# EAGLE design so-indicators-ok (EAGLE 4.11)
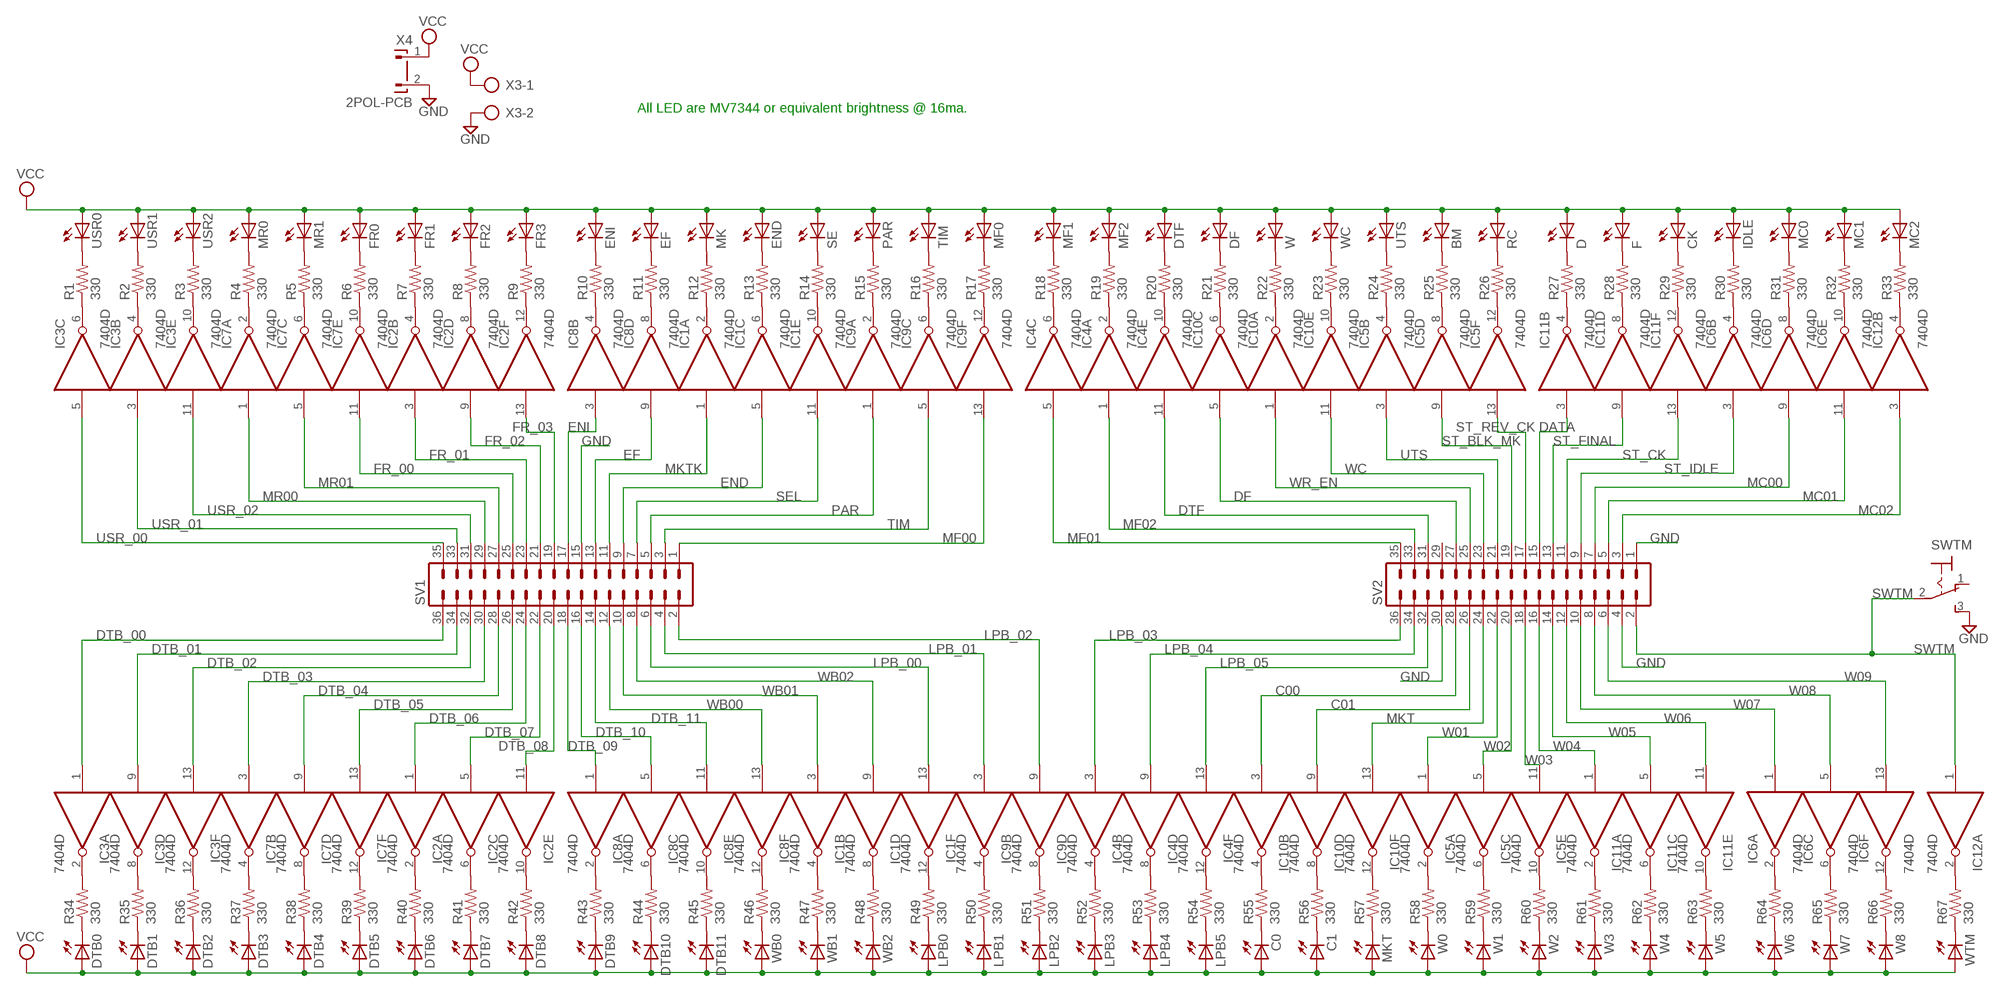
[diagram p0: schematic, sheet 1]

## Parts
BM  LED5MM  [LED5MM]
C0  LED5MM  [LED5MM]
C1  LED5MM  [LED5MM]
CK  LED5MM  [LED5MM]
D  LED5MM  [LED5MM]
DF  LED5MM  [LED5MM]
DTB0  LED5MM  [LED5MM]
DTB1  LED5MM  [LED5MM]
DTB2  LED5MM  [LED5MM]
DTB3  LED5MM  [LED5MM]
DTB4  LED5MM  [LED5MM]
DTB5  LED5MM  [LED5MM]
DTB6  LED5MM  [LED5MM]
DTB7  LED5MM  [LED5MM]
DTB8  LED5MM  [LED5MM]
DTB9  LED5MM  [LED5MM]
DTB10  LED5MM  [LED5MM]
DTB11  LED5MM  [LED5MM]
DTF  LED5MM  [LED5MM]
EF  LED5MM  [LED5MM]
END  LED5MM  [LED5MM]
ENI  LED5MM  [LED5MM]
F  LED5MM  [LED5MM]
FR0  LED5MM  [LED5MM]
FR1  LED5MM  [LED5MM]
FR2  LED5MM  [LED5MM]
FR3  LED5MM  [LED5MM]
IC1  7404D  [SO14]
IC2  7404D  [SO14]
IC3  7404D  [SO14]
IC4  7404D  [SO14]
IC5  7404D  [SO14]
IC6  7404D  [SO14]
IC7  7404D  [SO14]
IC8  7404D  [SO14]
IC9  7404D  [SO14]
IC10  7404D  [SO14]
IC11  7404D  [SO14]
IC12  7404D  [SO14]
IDLE  LED5MM  [LED5MM]
LPB0  LED5MM  [LED5MM]
LPB1  LED5MM  [LED5MM]
LPB2  LED5MM  [LED5MM]
LPB3  LED5MM  [LED5MM]
LPB4  LED5MM  [LED5MM]
LPB5  LED5MM  [LED5MM]
MC0  LED5MM  [LED5MM]
MC1  LED5MM  [LED5MM]
MC2  LED5MM  [LED5MM]
MF0  LED5MM  [LED5MM]
MF1  LED5MM  [LED5MM]
MF2  LED5MM  [LED5MM]
MK  LED5MM  [LED5MM]
MKT  LED5MM  [LED5MM]
MR0  LED5MM  [LED5MM]
MR1  LED5MM  [LED5MM]
PAR  LED5MM  [LED5MM]
R1  330  R-US_0207/10  [0207/10]
R2  330  R-US_0207/10  [0207/10]
R3  330  R-US_0207/10  [0207/10]
R4  330  R-US_0207/10  [0207/10]
R5  330  R-US_0207/10  [0207/10]
R6  330  R-US_0207/10  [0207/10]
R7  330  R-US_0207/10  [0207/10]
R8  330  R-US_0207/10  [0207/10]
R9  330  R-US_0207/10  [0207/10]
R10  330  R-US_0207/10  [0207/10]
R11  330  R-US_0207/10  [0207/10]
R12  330  R-US_0207/10  [0207/10]
R13  330  R-US_0207/10  [0207/10]
R14  330  R-US_0207/10  [0207/10]
R15  330  R-US_0207/10  [0207/10]
R16  330  R-US_0207/10  [0207/10]
R17  330  R-US_0207/10  [0207/10]
R18  330  R-US_0207/10  [0207/10]
R19  330  R-US_0207/10  [0207/10]
R20  330  R-US_0207/10  [0207/10]
R21  330  R-US_0207/10  [0207/10]
R22  330  R-US_0207/10  [0207/10]
R23  330  R-US_0207/10  [0207/10]
R24  330  R-US_0207/10  [0207/10]
R25  330  R-US_0207/10  [0207/10]
R26  330  R-US_0207/10  [0207/10]
R27  330  R-US_0207/10  [0207/10]
R28  330  R-US_0207/10  [0207/10]
R29  330  R-US_0207/10  [0207/10]
R30  330  R-US_0207/10  [0207/10]
R31  330  R-US_0207/10  [0207/10]
R32  330  R-US_0207/10  [0207/10]
R33  330  R-US_0207/10  [0207/10]
R34  330  R-US_0207/10  [0207/10]
R35  330  R-US_0207/10  [0207/10]
R36  330  R-US_0207/10  [0207/10]
R37  330  R-US_0207/10  [0207/10]
R38  330  R-US_0207/10  [0207/10]
R39  330  R-US_0207/10  [0207/10]
R40  330  R-US_0207/10  [0207/10]
R41  330  R-US_0207/10  [0207/10]
R42  330  R-US_0207/10  [0207/10]
R43  330  R-US_0207/10  [0207/10]
R44  330  R-US_0207/10  [0207/10]
R45  330  R-US_0207/10  [0207/10]
R46  330  R-US_0207/10  [0207/10]
R47  330  R-US_0207/10  [0207/10]
R48  330  R-US_0207/10  [0207/10]
R49  330  R-US_0207/10  [0207/10]
R50  330  R-US_0207/10  [0207/10]
R51  330  R-US_0207/10  [0207/10]
R52  330  R-US_0207/10  [0207/10]
R53  330  R-US_0207/10  [0207/10]
R54  330  R-US_0207/10  [0207/10]
R55  330  R-US_0207/10  [0207/10]
R56  330  R-US_0207/10  [0207/10]
R57  330  R-US_0207/10  [0207/10]
R58  330  R-US_0207/10  [0207/10]
R59  330  R-US_0207/10  [0207/10]
R60  330  R-US_0207/10  [0207/10]
R61  330  R-US_0207/10  [0207/10]
R62  330  R-US_0207/10  [0207/10]
R63  330  R-US_0207/10  [0207/10]
R64  330  R-US_0207/10  [0207/10]
R65  330  R-US_0207/10  [0207/10]
R66  330  R-US_0207/10  [0207/10]
R67  330  R-US_0207/10  [0207/10]
RC  LED5MM  [LED5MM]
SE  LED5MM  [LED5MM]
SV1  MA18-2  [MA18-2]
SV2  MA18-2  [MA18-2]
SWTM  M9040P  [M9040P]
TIM  LED5MM  [LED5MM]
USR0  LED5MM  [LED5MM]
USR1  LED5MM  [LED5MM]
USR2  LED5MM  [LED5MM]
UTS  LED5MM  [LED5MM]
W  LED5MM  [LED5MM]
W0  LED5MM  [LED5MM]
W1  LED5MM  [LED5MM]
W2  LED5MM  [LED5MM]
W3  LED5MM  [LED5MM]
W4  LED5MM  [LED5MM]
W5  LED5MM  [LED5MM]
W6  LED5MM  [LED5MM]
W7  LED5MM  [LED5MM]
W8  LED5MM  [LED5MM]
WB0  LED5MM  [LED5MM]
WB1  LED5MM  [LED5MM]
WB2  LED5MM  [LED5MM]
WC  LED5MM  [LED5MM]
WTM  LED5MM  [LED5MM]
X3  AK300/2  [AK300/2]
X4  2POL-PCB  [2POL-PCB]

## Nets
C00: IC10.3(B:I) SV2.28
C01: IC10.9(D:I) SV2.26
DATA: IC11.3(B:I) SV2.15
DF: IC10.5(C:I) SV2.27
DTB_00: IC3.1(A:I) SV1.36
DTB_01: IC3.9(D:I) SV1.34
DTB_02: IC3.13(F:I) SV1.32
DTB_03: IC7.3(B:I) SV1.30
DTB_04: IC7.9(D:I) SV1.28
DTB_05: IC7.13(F:I) SV1.26
DTB_06: IC2.1(A:I) SV1.24
DTB_07: IC2.5(C:I) SV1.22
DTB_08: IC2.11(E:I) SV1.20
DTB_09: IC8.1(A:I) SV1.18
DTB_10: IC8.5(C:I) SV1.16
DTB_11: IC8.11(E:I) SV1.14
DTF: IC4.11(E:I) SV2.31
EF: IC8.9(D:I) SV1.13
END: IC1.5(C:I) SV1.9
ENI: IC8.3(B:I) SV1.17
FR_00: IC7.11(E:I) SV1.25
FR_01: IC2.3(B:I) SV1.23
FR_02: IC2.9(D:I) SV1.21
FR_03: IC2.13(F:I) SV1.19
GND: SV1.15 SV2.1 SV2.4 SV2.30 SWTM.3(S) X3.2 X4.2
LPB_00: IC1.13(F:I) SV1.6
LPB_01: IC9.3(B:I) SV1.4
LPB_02: IC9.9(D:I) SV1.2
LPB_03: IC4.3(B:I) SV2.36
LPB_04: IC4.9(D:I) SV2.34
LPB_05: IC4.13(F:I) SV2.32
MC00: IC6.9(D:I) SV2.7
MC01: IC6.11(E:I) SV2.5
MC02: IC12.3(B:I) SV2.3
MF00: IC9.13(F:I) SV1.1
MF01: IC4.5(C:I) SV2.35
MF02: IC4.1(A:I) SV2.33
MKT: IC10.13(F:I) SV2.24
MKTK: IC1.1(A:I) SV1.11
MR00: IC7.1(A:I) SV1.29
MR01: IC7.5(C:I) SV1.27
N$1: R1.2 USR0.K(C)
N$2: R2.2 USR1.K(C)
N$3: R3.2 USR2.K(C)
N$4: MR0.K(C) R4.2
N$5: MR1.K(C) R5.2
N$6: FR0.K(C) R6.2
N$7: FR1.K(C) R7.2
N$8: FR2.K(C) R8.2
N$9: FR3.K(C) R9.2
N$10: ENI.K(C) R10.2
N$11: EF.K(C) R11.2
N$12: MK.K(C) R12.2
N$13: END.K(C) R13.2
N$14: R14.2 SE.K(C)
N$15: PAR.K(C) R15.2
N$16: R16.2 TIM.K(C)
N$17: MF0.K(C) R17.2
N$18: MF1.K(C) R18.2
N$19: MF2.K(C) R19.2
N$20: IC3.6(C:O) R1.1
N$21: IC3.4(B:O) R2.1
N$22: IC3.10(E:O) R3.1
N$23: IC7.2(A:O) R4.1
N$24: IC7.6(C:O) R5.1
N$25: IC7.10(E:O) R6.1
N$26: IC2.4(B:O) R7.1
N$27: IC2.8(D:O) R8.1
N$28: IC2.12(F:O) R9.1
N$29: IC8.4(B:O) R10.1
N$30: IC8.8(D:O) R11.1
N$31: IC1.2(A:O) R12.1
N$32: IC1.6(C:O) R13.1
N$33: IC1.10(E:O) R14.1
N$34: IC9.2(A:O) R15.1
N$35: IC9.6(C:O) R16.1
N$36: IC9.12(F:O) R17.1
N$37: IC4.6(C:O) R18.1
N$38: DTF.K(C) R20.2
N$57: DF.K(C) R21.2
N$58: R22.2 W.K(C)
N$59: R23.2 WC.K(C)
N$60: R24.2 UTS.K(C)
N$61: BM.K(C) R25.2
N$62: R26.2 RC.K(C)
N$63: D.K(C) R27.2
N$64: F.K(C) R28.2
N$65: CK.K(C) R29.2
N$66: IDLE.K(C) R30.2
N$67: MC0.K(C) R31.2
N$68: MC1.K(C) R32.2
N$69: MC2.K(C) R33.2
N$70: IC4.2(A:O) R19.1
N$71: IC4.10(E:O) R20.1
N$72: IC10.6(C:O) R21.1
N$73: IC10.10(E:O) R23.1
N$74: IC10.2(A:O) R22.1
N$75: IC5.4(B:O) R24.1
N$76: IC5.8(D:O) R25.1
N$77: IC5.12(F:O) R26.1
N$78: IC11.4(B:O) R27.1
N$79: IC11.8(D:O) R28.1
N$80: IC11.12(F:O) R29.1
N$81: IC6.4(B:O) R30.1
N$82: IC6.8(D:O) R31.1
N$83: IC6.10(E:O) R32.1
N$84: IC12.4(B:O) R33.1
N$89: DTB0.K(C) R34.1
N$90: DTB1.K(C) R35.1
N$91: DTB2.K(C) R36.1
N$92: DTB3.K(C) R37.1
N$93: DTB4.K(C) R38.1
N$94: DTB5.K(C) R39.1
N$95: DTB6.K(C) R40.1
N$96: DTB7.K(C) R41.1
N$97: DTB8.K(C) R42.1
N$98: DTB9.K(C) R43.1
N$99: DTB10.K(C) R44.1
N$100: DTB11.K(C) R45.1
N$101: R46.1 WB0.K(C)
N$102: R47.1 WB1.K(C)
N$103: R48.1 WB2.K(C)
N$104: LPB0.K(C) R49.1
N$105: LPB1.K(C) R50.1
N$106: LPB2.K(C) R51.1
N$107: LPB3.K(C) R52.1
N$108: LPB4.K(C) R53.1
N$109: LPB5.K(C) R54.1
N$110: C0.K(C) R55.1
N$111: C1.K(C) R56.1
N$112: MKT.K(C) R57.1
N$113: R58.1 W0.K(C)
N$114: R59.1 W1.K(C)
N$115: R60.1 W2.K(C)
N$116: R61.1 W3.K(C)
N$117: R62.1 W4.K(C)
N$118: R63.1 W5.K(C)
N$119: R64.1 W6.K(C)
N$120: R65.1 W7.K(C)
N$121: R66.1 W8.K(C)
N$122: R67.1 WTM.K(C)
N$123: IC3.2(A:O) R34.2
N$124: IC3.8(D:O) R35.2
N$125: IC3.12(F:O) R36.2
N$126: IC7.4(B:O) R37.2
N$127: IC7.8(D:O) R38.2
N$128: IC7.12(F:O) R39.2
N$129: IC2.2(A:O) R40.2
N$130: IC2.6(C:O) R41.2
N$131: IC2.10(E:O) R42.2
N$132: IC8.2(A:O) R43.2
N$133: IC8.6(C:O) R44.2
N$134: IC8.10(E:O) R45.2
N$135: IC8.12(F:O) R46.2
N$136: IC1.4(B:O) R47.2
N$137: IC1.8(D:O) R48.2
N$138: IC1.12(F:O) R49.2
N$139: IC9.4(B:O) R50.2
N$140: IC9.8(D:O) R51.2
N$141: IC4.4(B:O) R52.2
N$142: IC4.8(D:O) R53.2
N$143: IC4.12(F:O) R54.2
N$144: IC10.4(B:O) R55.2
N$145: IC10.8(D:O) R56.2
N$146: IC10.12(F:O) R57.2
N$147: IC5.2(A:O) R58.2
N$148: IC5.6(C:O) R59.2
N$149: IC5.10(E:O) R60.2
N$150: IC11.2(A:O) R61.2
N$151: IC11.6(C:O) R62.2
N$152: IC11.10(E:O) R63.2
N$153: IC6.2(A:O) R64.2
N$154: IC6.6(C:O) R65.2
N$155: IC6.12(F:O) R66.2
N$190: IC12.2(A:O) R67.2
PAR: IC9.1(A:I) SV1.5
SEL: IC1.11(E:I) SV1.7
ST_BLK_MK: IC5.9(D:I) SV2.19
ST_CK: IC11.13(F:I) SV2.11
ST_FINAL: IC11.9(D:I) SV2.13
ST_IDLE: IC6.3(B:I) SV2.9
ST_REV_CK: IC5.13(F:I) SV2.17
SWTM: IC12.1(A:I) SV2.2 SWTM.2(P)
TIM: IC9.5(C:I) SV1.3
USR_00: IC3.5(C:I) SV1.35
USR_01: IC3.3(B:I) SV1.33
USR_02: IC3.11(E:I) SV1.31
UTS: IC5.3(B:I) SV2.21
VCC: BM.A C0.A C1.A CK.A D.A DF.A DTB0.A DTB1.A DTB2.A DTB3.A DTB4.A DTB5.A DTB6.A DTB7.A DTB8.A DTB9.A DTB10.A DTB11.A DTF.A EF.A END.A ENI.A F.A FR0.A FR1.A FR2.A FR3.A IDLE.A LPB0.A LPB1.A LPB2.A LPB3.A LPB4.A LPB5.A MC0.A MC1.A MC2.A MF0.A MF1.A MF2.A MK.A MKT.A MR0.A MR1.A PAR.A RC.A SE.A TIM.A USR0.A USR1.A USR2.A UTS.A W0.A W1.A W2.A W3.A W4.A W5.A W6.A W7.A W8.A W.A WB0.A WB1.A WB2.A WC.A WTM.A X3.1 X4.1
W01: IC5.1(A:I) SV2.22
W02: IC5.5(C:I) SV2.20
W03: IC5.11(E:I) SV2.18
W04: IC11.1(A:I) SV2.16
W05: IC11.5(C:I) SV2.14
W06: IC11.11(E:I) SV2.12
W07: IC6.1(A:I) SV2.10
W08: IC6.5(C:I) SV2.8
W09: IC6.13(F:I) SV2.6
WB00: IC8.13(F:I) SV1.12
WB01: IC1.3(B:I) SV1.10
WB02: IC1.9(D:I) SV1.8
WC: IC10.11(E:I) SV2.23
WR_EN: IC10.1(A:I) SV2.25
Unconnected: IC9.10(E:O) IC9.11(E:I) IC12.5(C:I) IC12.6(C:O) IC12.8(D:O) IC12.9(D:I) IC12.10(E:O) IC12.11(E:I) IC12.12(F:O) IC12.13(F:I) SV2.29 SWTM.1(O)

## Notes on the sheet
- All LED are MV7344 or equivalent brightness @ 16ma.

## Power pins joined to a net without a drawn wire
GND: IC1.7(P:GND) IC2.7(P:GND) IC3.7(P:GND) IC4.7(P:GND) IC5.7(P:GND) IC6.7(P:GND) IC7.7(P:GND) IC8.7(P:GND) IC9.7(P:GND) IC10.7(P:GND) IC11.7(P:GND) IC12.7(P:GND)
VCC: IC1.14(P:VCC) IC2.14(P:VCC) IC3.14(P:VCC) IC4.14(P:VCC) IC5.14(P:VCC) IC6.14(P:VCC) IC7.14(P:VCC) IC8.14(P:VCC) IC9.14(P:VCC) IC10.14(P:VCC) IC11.14(P:VCC) IC12.14(P:VCC)

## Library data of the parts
BM C0 C1 CK D DF DTB0 DTB1-DTB11 DTF EF END ENI F FR0 FR1-FR3 IDLE LPB0 LPB1-LPB5 MC0 MC1 MC2 MF0 MF1 MF2 MK MKT MR0 MR1 PAR RC SE TIM USR0 USR1 USR2 UTS W W0 W1-W8 WB0 WB1 WB2 WC WTM = led:LED: LED
IC1-IC12 = 74xx-us:74*04: Hex INVERTER
R1-R67 = rcl:R-US_: RESISTOR, American symbol
SV1 SV2 = con-lstb:MA18-2: PIN HEADER
SWTM = switch:M9040P: TOGGLE SWITCH Marquardt
X3 = con-ptr500:AK300/2: CONNECTOR
X4 = con-friwo:2POL-PCB: PCB SUPPLY CONNECTOR

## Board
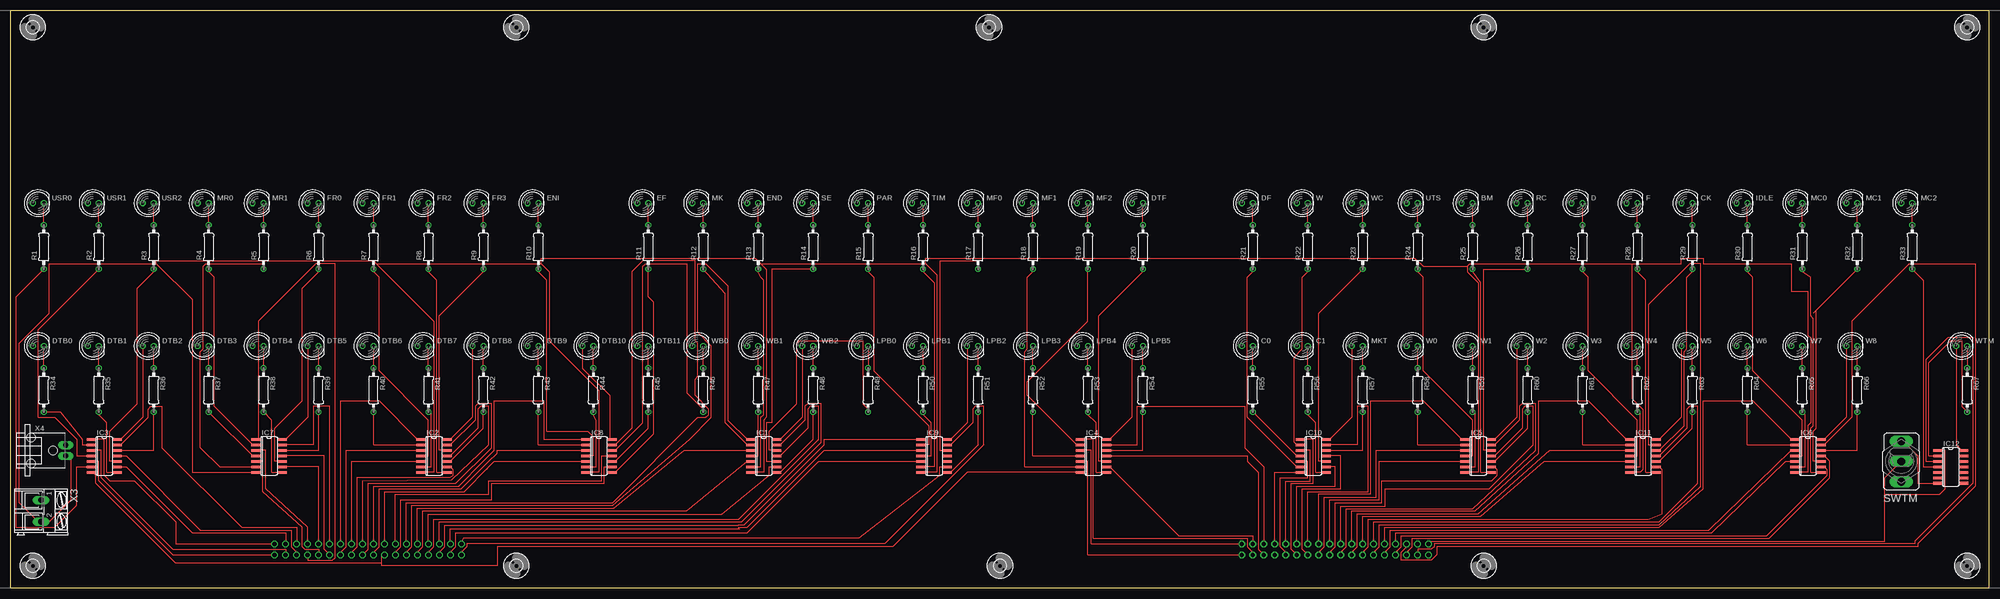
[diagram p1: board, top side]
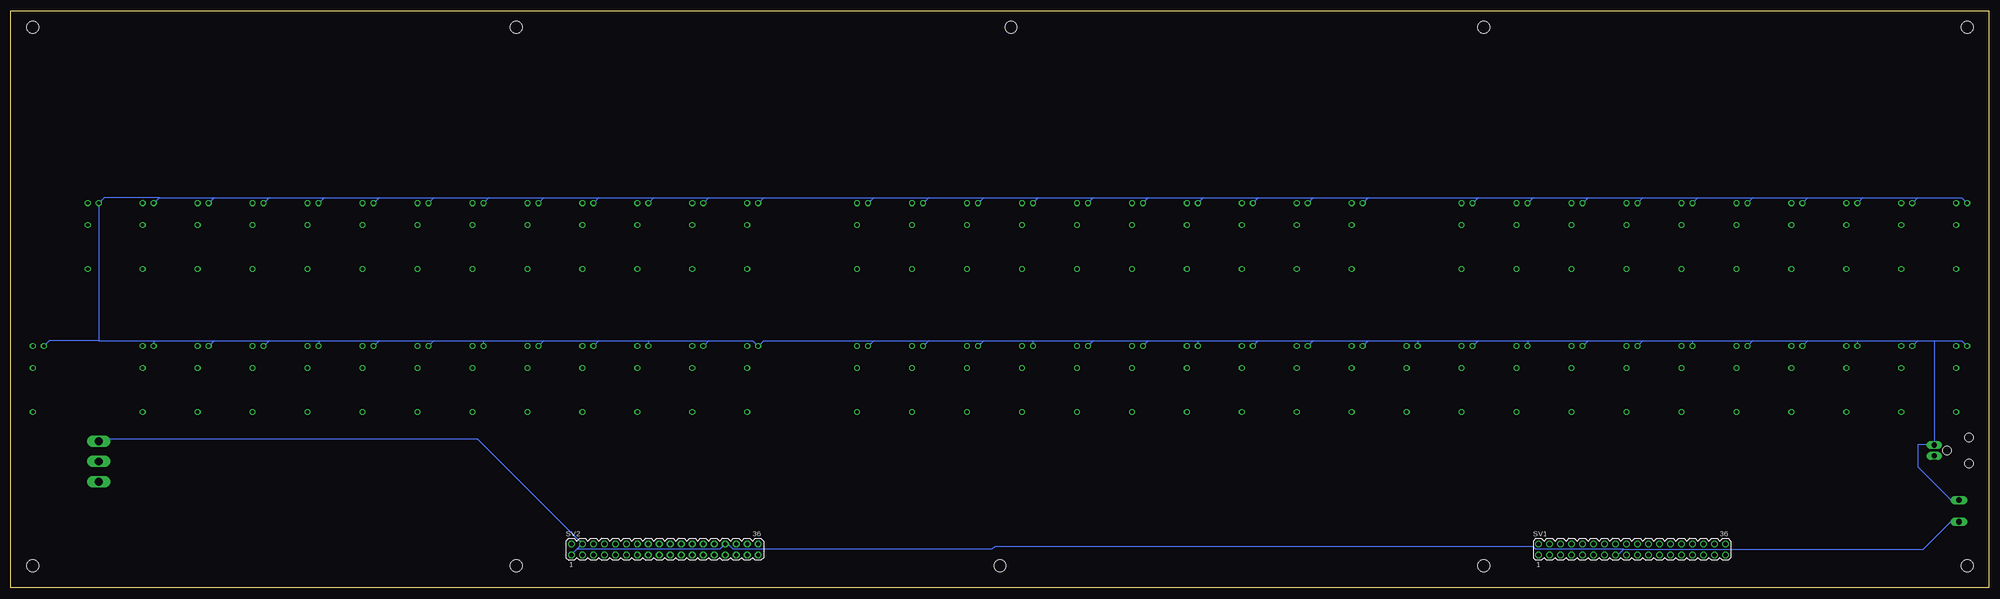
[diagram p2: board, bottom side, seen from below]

Size 457.2 x 133.35 mm. Coordinates in mm from the lower left corner, seen from the top.
Outline: 0,0 457.2,0 457.2,133.35 0,133.35 0,0
Copper layers (1*16): Top 0.035mm / dielectric 1.5mm / Bottom 0.035mm
Design rules "default": minimum track width 10mil, minimum drill 24mil, track to track 8mil, track to pad 8mil, pad to pad 8mil, via to via 8mil, smd to smd 8mil, copper to edge 40mil, drill to drill 8mil, minimum pad ring 10mil, minimum via ring 8mil, stop-mask expansion 4mil, vias tented up to drill 0mil, thermal gap 10mil

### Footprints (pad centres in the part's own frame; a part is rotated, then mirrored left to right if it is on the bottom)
LED5MM = drill 0.813 octagon: A -1.27,0; K 1.27,0
SO14 = smd 0.66 x 2.032: 1 -3.81,-3.073; 2 -2.54,-3.073; 3 -1.27,-3.073; 4 0,-3.073; 5 1.27,-3.073; 6 2.54,-3.073; 7 3.81,-3.073; 8 3.81,3.073; 9 2.54,3.073; 10 1.27,3.073; 11 0,3.073; 12 -1.27,3.073; 13 -2.54,3.073; 14 -3.81,3.073
0207/10 = drill 0.813 octagon: 1 -5.08,0; 2 5.08,0
MA18-2 = drill 1.016 octagon: 1 -21.59,-1.27; 2 -21.59,1.27; 3 -19.05,-1.27; 4 -19.05,1.27; 5 -16.51,-1.27; 6 -16.51,1.27; 7 -13.97,-1.27; 8 -13.97,1.27; 9 -11.43,-1.27; 10 -11.43,1.27; 11 -8.89,-1.27; 12 -8.89,1.27; 13 -6.35,-1.27; 14 -6.35,1.27; 15 -3.81,-1.27; 16 -3.81,1.27; 17 -1.27,-1.27; 18 -1.27,1.27; 19 1.27,-1.27; 20 1.27,1.27; 21 3.81,-1.27; 22 3.81,1.27; 23 6.35,-1.27; 24 6.35,1.27; 25 8.89,-1.27; 26 8.89,1.27; 27 11.43,-1.27; 28 11.43,1.27; 29 13.97,-1.27; 30 13.97,1.27; 31 16.51,-1.27; 32 16.51,1.27; 33 19.05,-1.27; 34 19.05,1.27; 35 21.59,-1.27; 36 21.59,1.27
M9040P = drill 1.803 long: 1 0,4.699; 2 0,0; 3 0,-4.699
2,8 = hole 2.8: 0,0
AK300/2 = drill 1.321 long: 1 -2.515,0; 2 2.489,0
2POL-PCB = drill 1.2 long: 1 -1.25,11.6; 2 1.25,11.6 | hole 2: -3,3.6; 3,3.6; 0,8.6

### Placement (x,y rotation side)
BM  336.55,88.9 0 top
C0  285.75,55.88 0 top
C1  298.45,55.88 0 top
CK  387.35,88.9 0 top
D  361.95,88.9 0 top
DF  285.75,88.9 0 top
DTB0  6.35,55.88 0 top
DTB1  19.05,55.88 0 top
DTB2  31.75,55.88 0 top
DTB3  44.45,55.88 0 top
DTB4  57.15,55.88 0 top
DTB5  69.85,55.88 0 top
DTB6  82.55,55.88 0 top
DTB7  95.25,55.88 0 top
DTB8  107.95,55.88 0 top
DTB9  120.65,55.88 0 top
DTB10  133.35,55.88 0 top
DTB11  146.05,55.88 0 top
DTF  260.35,88.9 0 top
EF  146.05,88.9 0 top
END  171.45,88.9 0 top
ENI  120.65,88.9 0 top
F  374.65,88.9 0 top
FR0  69.85,88.9 0 top
FR1  82.55,88.9 0 top
FR2  95.25,88.9 0 top
FR3  107.95,88.9 0 top
IC1  173.99,30.48 270 top
IC2  97.79,30.48 270 top
IC3  21.59,30.48 270 top
IC4  250.19,30.48 270 top
IC5  339.09,30.48 270 top
IC6  415.29,30.48 270 top
IC7  59.69,30.48 270 top
IC8  135.89,30.48 270 top
IC9  213.36,30.48 270 top
IC10  300.99,30.48 270 top
IC11  377.19,30.48 270 top
IC12  448.31,27.94 270 top
IDLE  400.05,88.9 0 top
LPB0  196.85,55.88 0 top
LPB1  209.55,55.88 0 top
LPB2  222.25,55.88 0 top
LPB3  234.95,55.88 0 top
LPB4  247.65,55.88 0 top
LPB5  260.35,55.88 0 top
MC0  412.75,88.9 0 top
MC1  425.45,88.9 0 top
MC2  438.15,88.9 0 top
MF0  222.25,88.9 0 top
MF1  234.95,88.9 0 top
MF2  247.65,88.9 0 top
MK  158.75,88.9 0 top
MKT  311.15,55.88 0 top
MR0  44.45,88.9 0 top
MR1  57.15,88.9 0 top
PAR  196.85,88.9 0 top
R1  7.62,78.74 90 top
R2  20.32,78.74 90 top
R3  33.02,78.74 90 top
R4  45.72,78.74 90 top
R5  58.42,78.74 90 top
R6  71.12,78.74 90 top
R7  83.82,78.74 90 top
R8  96.52,78.74 90 top
R9  109.22,78.74 90 top
R10  121.92,78.74 90 top
R11  147.32,78.74 90 top
R12  160.02,78.74 90 top
R13  172.72,78.74 90 top
R14  185.42,78.74 90 top
R15  198.12,78.74 90 top
R16  210.82,78.74 90 top
R17  223.52,78.74 90 top
R18  236.22,78.74 90 top
R19  248.92,78.74 90 top
R20  261.62,78.74 90 top
R21  287.02,78.74 90 top
R22  299.72,78.74 90 top
R23  312.42,78.74 90 top
R24  325.12,78.74 90 top
R25  337.82,78.74 90 top
R26  350.52,78.74 90 top
R27  363.22,78.74 90 top
R28  375.92,78.74 90 top
R29  388.62,78.74 90 top
R30  401.32,78.74 90 top
R31  414.02,78.74 90 top
R32  426.72,78.74 90 top
R33  439.42,78.74 90 top
R34  7.62,45.72 270 top
R35  20.32,45.72 270 top
R36  33.02,45.72 270 top
R37  45.72,45.72 270 top
R38  58.42,45.72 270 top
R39  71.12,45.72 270 top
R40  83.82,45.72 270 top
R41  96.52,45.72 270 top
R42  109.22,45.72 270 top
R43  121.92,45.72 270 top
R44  134.62,45.72 270 top
R45  147.32,45.72 270 top
R46  160.02,45.72 270 top
R47  172.72,45.72 270 top
R48  185.42,45.72 270 top
R49  198.12,45.72 270 top
R50  210.82,45.72 270 top
R51  223.52,45.72 270 top
R52  236.22,45.72 270 top
R53  248.92,45.72 270 top
R54  261.62,45.72 270 top
R55  287.02,45.72 270 top
R56  299.72,45.72 270 top
R57  312.42,45.72 270 top
R58  325.12,45.72 270 top
R59  337.82,45.72 270 top
R60  350.52,45.72 270 top
R61  363.22,45.72 270 top
R62  375.92,45.72 270 top
R63  388.62,45.72 270 top
R64  401.32,45.72 270 top
R65  414.02,45.72 270 top
R66  426.72,45.72 270 top
R67  452.12,45.72 270 top
RC  349.25,88.9 0 top
SE  184.15,88.9 0 top
SV1  82.55,8.89 0 bottom
SV2  306.07,8.89 0 bottom
SWTM  436.88,29.21 180 top
TIM  209.55,88.9 0 top
U$1  [2,8]  5.08,5.08 0 top
U$2  [2,8]  5.08,129.54 0 top
U$3  [2,8]  116.84,5.08 0 top
U$4  [2,8]  116.84,129.54 0 top
U$5  [2,8]  226.06,129.54 0 top
U$6  [2,8]  228.6,5.08 0 top
U$7  [2,8]  340.36,129.54 0 top
U$8  [2,8]  340.36,5.08 0 top
U$9  [2,8]  452.12,129.54 0 top
U$10  [2,8]  452.12,5.08 0 top
USR0  6.35,88.9 0 top
USR1  19.05,88.9 0 top
USR2  31.75,88.9 0 top
UTS  323.85,88.9 0 top
W  298.45,88.9 0 top
W0  323.85,55.88 0 top
W1  336.55,55.88 0 top
W2  349.25,55.88 0 top
W3  361.95,55.88 0 top
W4  374.65,55.88 0 top
W5  387.35,55.88 0 top
W6  400.05,55.88 0 top
W7  412.75,55.88 0 top
W8  425.45,55.88 0 top
WB0  158.75,55.88 0 top
WB1  171.45,55.88 0 top
WB2  184.15,55.88 0 top
WC  311.15,88.9 0 top
WTM  450.85,55.88 0 top
X3  6.99,17.78 270 top
X4  1.11,31.75 270 top

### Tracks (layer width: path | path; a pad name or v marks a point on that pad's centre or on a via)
C00
  Top 0.254: 294.64,24.61 SV2.28 294.64,24.61 | IC10.3 298.45,31.75 300.36,31.75 300.36,24.61 294.64,24.61
C01
  Top 0.254: IC10.9 306.07,27.94 306.07,23.5 297.18,23.5 SV2.26
DATA
  Top 0.254: 355.6,31.75 IC11.3 355.6,31.75 | 355.6,31.75 339.09,17.15 311.15,17.15 311.15,9.53 309.88,8.26 SV2.15
DF
  Top 0.254: IC10.5 298.45,29.21 299.72,29.21 299.72,25.4 293.37,25.4 293.37,9.53 294.64,8.26 SV2.27
DTB_00
  Top 0.254: SV1.36 38.1,10.16 38.1,15.24 28.57,24.77 22.86,24.77 21.59,26.04 21.59,34.29 19.05,34.29 | 19.05,34.29 IC3.1 19.05,34.29
DTB_01
  Top 0.254: SV1.34 63.5,12.7 41.91,12.7 26.67,27.94 25.4,27.94 IC3.9
DTB_02
  Top 0.254: IC3.13 25.4,33.02 31.75,39.37 31.75,41.28 32.38,41.91 34.92,41.91 34.92,32.39 53.34,13.97 66.04,13.97 66.04,10.8 SV1.32
DTB_03
  Top 0.254: IC7.3 57.15,31.75 58.9,31.75 58.9,22.86 68.58,13.97 68.58,10.8 SV1.30
DTB_04
  Top 0.254: SV1.28 71.12,27.94 63.5,27.94 IC7.9
DTB_05
  Top 0.254: SV1.26 73.66,41.91 69.85,41.91 69.85,33.02 63.5,33.02 IC7.13
DTB_06
  Top 0.254: IC2.1 93.98,34.29 85.09,43.18 76.2,43.18 76.2,10.8 SV1.24
DTB_07
  Top 0.254: IC2.5 93.98,29.21 78.74,29.21 78.74,10.8 SV1.22
DTB_08
  Top 0.254: IC2.11 101.6,30.48 107.95,36.83 107.95,41.28 108.58,41.91 110.49,41.91 110.49,33.02 101.92,24.92 81.28,24.77 81.28,19.69 81.28,10.8 SV1.20
DTB_09
  Top 0.254: 132.08,34.29 IC8.1 | 132.08,34.29 IC8.1 | 132.08,34.29 IC8.1 | 132.08,34.29 123.19,34.29 123.19,43.18 111.76,43.18 111.76,34.29 111.76,31.75 109.22,29.21 103.5,23.5 83.82,23.5 83.82,10.8 SV1.18 | 132.08,34.29 IC8.1
DTB_10
  Top 0.254: IC8.5 132.08,29.21 111.76,29.21 110.49,27.94 | SV1.16 86.36,10.8 86.36,22.07 86.36,22.23 104.78,22.23 110.49,27.94 | 110.49,27.94 109.86,27.31
DTB_11
  Top 0.254: IC8.11 138.43,30.48 136.53,30.48 136.53,24.77 110.49,24.77 110.49,21.59 88.9,21.59 88.9,10.8 SV1.14
DTF
  Top 0.254: SV2.31 288.29,8.89 288.29,26.67 285.75,29.21 285.75,30.48 254,30.48 IC4.11
EF
  Top 0.254: IC8.9 138.43,27.94 137.16,27.94 137.16,24.13 111.12,24.13 111.12,20.32 90.17,20.32 90.17,10.8 90.17,9.53 88.9,8.26 SV1.13
END
  Top 0.254: IC1.5 170.18,29.21 156.21,17.78 95.25,17.78 95.25,13.65 95.25,10.8 95.25,9.53 93.98,8.26 SV1.9
ENI
  Top 0.254: 83.82,8.26 SV1.17 83.82,8.26 | IC8.3 132.08,31.75 112.39,31.75 112.39,31.12 110.49,29.21 105.41,24.13 104.14,22.86 85.09,22.86 85.09,10.8 85.09,9.53 83.82,8.26
FR_00
  Top 0.254: SV1.25 72.39,8.89 72.39,30.48 63.5,30.48 IC7.11
FR_01
  Top 0.254: IC2.3 93.98,31.75 77.47,31.75 77.47,9.53 76.2,8.26 SV1.23
FR_02
  Top 0.254: IC2.9 101.6,27.94 102.23,27.31 102.23,26.04 101.6,25.56 91.44,25.56 87.31,25.56 80.01,25.56 80.01,9.53 78.74,8.26 SV1.21
FR_03
  Top 0.254: SV1.19 82.55,8.89 82.55,22.86 82.55,24.13 101.6,24.13 102.87,24.13 111.12,32.39 111.12,42.55 107.95,42.55 107.31,41.91 107.31,38.74 101.6,33.02 IC2.13
GND
  Top 0.254: SV2.30 292.1,26.67 297.18,26.67 IC10.7 | IC12.7 444.5,24.13 440.69,24.13 440.69,30.48 438.15,33.02 SWTM.3 434.98,33.02 | X4.2 13.97,30.48 13.97,26.67 13.97,20.32 8.89,15.24 X3.2 5.71,15.88 1.91,19.69 1.91,56.52 8.89,63.5 8.89,74.93 33.66,74.93 | 85.72,5.72 38.1,5.72 19.68,24.13 19.68,26.04 19.05,26.67 IC3.7 | 85.72,5.72 85.72,7.62 SV1.15 | 85.72,5.72 85.72,5.08 95.25,5.08 97.79,5.08 112.39,5.08 112.39,9.53 203.84,9.53 220.98,26.67 246.38,26.67 IC4.7 | IC9.7 209.55,26.67 IC9.7 | 336.55,74.3 336.55,73.03 339.09,70.49 339.09,26.67 336.55,26.67 IC5.7 | 336.55,74.3 337.19,74.93 374.65,74.93 | 374.65,74.93 374.65,43.82 377.19,41.28 377.19,27.31 376.56,26.67 374.65,26.67 IC11.7 | 33.66,74.93 41.91,66.68 41.91,26.67 55.88,26.67 IC7.7 | 84.45,74.93 83.82,75.57 33.66,75.57 33.66,74.93 | 84.45,74.93 97.79,61.6 97.79,26.67 95.25,26.67 IC2.7 | 122.56,74.93 124.46,73.03 124.46,57.15 135.89,45.72 135.89,26.67 133.35,26.67 IC8.7 | 84.45,74.93 122.56,74.93 | 173.35,74.93 172.09,76.2 122.56,76.2 122.56,74.93 | 173.35,74.93 174.62,73.66 174.62,39.37 173.99,38.74 173.99,26.67 171.45,26.67 IC1.7 | 211.46,74.93 214,72.39 214,26.67 210.82,26.67 IC9.7 | 173.35,74.93 211.46,74.93 | 336.55,74.3 326.39,74.3 324.49,76.2 211.46,76.2 211.46,74.93 | IC6.7 412.75,26.67 415.29,26.67 415.29,37.47 415.93,38.1 415.93,57.79 415.29,58.42 415.29,68.58 411.48,68.58 411.48,74.93 391.16,74.93 391.16,76.2 386.08,76.2 386.08,74.93 374.65,74.93
  Bottom 0.254: 326.39,8.89 SV2.4 325.12,10.8 325.75,10.8 349.25,34.29 434.34,34.29 SWTM.3 | 326.39,8.89 SV2.1 | 326.39,8.89 293.37,8.89 SV2.30 291.46,10.16 290.19,8.89 230.5,8.89 229.87,9.53 105.41,9.53 104.78,8.89 84.45,8.89 | 84.45,8.89 85.72,7.62 SV1.15 | 84.45,8.89 15.24,8.89 8.89,15.24 X3.2
LPB_00
  Top 0.254: 167.64,15.24 99.06,15.24 99.06,10.8 SV1.6 | 167.64,15.24 | 167.64,15.24 | IC1.13 177.8,33.02 183.51,38.74 183.51,41.91 184.15,42.55 187.32,42.55 187.32,33.66 168.91,15.24 167.64,15.24 | 167.64,15.24 | 167.64,15.24
LPB_01
  Top 0.254: 168.28,13.65 101.6,13.65 101.6,10.8 SV1.4 | 168.28,13.65 168.43,13.65 | IC9.3 209.55,31.75 190.5,31.75 187.96,31.75 170.18,13.97 168.28,13.97 168.28,13.65
LPB_02
  Top 0.254: IC9.9 215.9,27.94 214.63,27.94 214.63,26.04 196.06,11.59 104.62,11.59 SV1.2
LPB_03
  Top 0.254: IC4.3 247.65,31.75 249.71,31.75 249.71,26.04 249.71,10.16 283.85,10.16 SV2.36
LPB_04
  Top 0.254: 254,27.94 IC4.9 254,27.94 | 254,27.94 269.88,12.07 287.02,12.07 287.02,10.8 SV2.34
LPB_05
  Top 0.254: SV2.32 289.56,27.94 285.75,31.75 285.12,32.39 285.12,41.91 260.35,41.91 260.35,33.02 254,33.02 IC4.13
MC00
  Top 0.254: IC6.9 419.1,27.94 419.74,27.31 419.74,26.04 405.76,12.07 321.31,12.07 321.31,9.53 320.04,8.26 SV2.7
MC01
  Top 0.254: 419.1,30.48 IC6.11 419.1,30.48 | SV2.5 322.58,8.26 323.85,9.53 323.85,11.43 405.13,11.43 406.4,11.43 420.37,25.4 420.37,29.21 419.1,30.48
MC02
  Top 0.254: IC12.3 444.5,29.21 442.6,29.21 442.6,52.71 447.68,57.79 453.39,57.79 453.39,24.13 440.06,10.8 440.06,10.16 328.93,10.16 328.93,9.53 328.3,8.89 325.12,8.89 325.12,8.26 SV2.3
MF00
  Top 0.254: SV1.1 104.14,8.26 105.41,9.53 105.41,10.16 201.93,10.16 217.81,26.04 224.79,33.02 224.79,41.91 222.88,41.91 222.25,41.28 222.25,38.1 217.17,33.02 IC9.13
MF01
  Top 0.254: IC4.5 247.65,29.21 248.92,29.21 248.92,25.72 248.92,7.62 283.85,7.62 SV2.35
MF02
  Top 0.254: IC4.1 247.65,34.29 250.19,34.29 250.19,26.04 250.19,11.43 285.75,11.43 285.75,9.53 287.02,8.26 SV2.33
MKT
  Top 0.254: SV2.24 299.72,22.23 313.69,22.23 313.69,41.91 311.15,41.91 311.15,33.02 304.8,33.02 IC10.13
MKTK
  Top 0.254: SV1.11 91.44,8.26 92.71,9.53 92.71,10.8 92.71,19.05 139.06,19.05 156.84,34.29 161.93,39.37 161.93,46.99 161.93,55.88 158.75,59.06 158.75,74.93 160.66,74.93 165.74,69.85 165.74,38.74 170.18,34.29 IC1.1
MR00
  Top 0.254: IC7.1 57.15,34.29 57.15,61.6 70.48,74.93 74.93,74.93 74.93,6.99 74.3,6.35 68.58,6.35 68.58,6.99 SV1.29
MR01
  Top 0.254: IC7.5 57.15,29.21 58.26,29.21 58.26,22.23 67.31,13.97 67.31,9.53 67.94,8.89 71.12,8.89 71.12,8.26 SV1.27
N$1
  Top 0.254: R1.2 USR0.K
N$2
  Top 0.254: R2.2 USR1.K
N$3
  Top 0.254: R3.2 USR2.K
N$4
  Top 0.254: R4.2 MR0.K
N$5
  Top 0.254: R5.2 MR1.K
N$6
  Top 0.254: R6.2 FR0.K
N$7
  Top 0.254: R7.2 FR1.K
N$8
  Top 0.254: R8.2 FR2.K
N$9
  Top 0.254: R9.2 FR3.K
N$10
  Top 0.254: R10.2 ENI.K
N$11
  Top 0.254: R11.2 EF.K
N$12
  Top 0.254: R12.2 MK.K
N$13
  Top 0.254: R13.2 END.K
N$14
  Top 0.254: R14.2 SE.K
N$15
  Top 0.254: R15.2 PAR.K
N$16
  Top 0.254: R16.2 TIM.K
N$17
  Top 0.254: R17.2 MF0.K
N$18
  Top 0.254: R18.2 MF1.K
N$19
  Top 0.254: R19.2 MF2.K
N$20
  Top 0.254: R1.1 1.27,67.31 1.27,13.97 10.16,13.97 15.24,19.05 15.24,27.94 17.78,27.94 IC3.6
N$21
  Top 0.254: R2.1 6.35,59.69 6.35,39.37 10.16,39.37 15.24,34.29 15.24,30.48 17.78,30.48 IC3.4
N$22
  Top 0.254: IC3.10 24.13,29.21 22.86,29.21 22.86,36.2 29.21,42.55 29.21,69.22 33.02,73.03 R3.1
N$23
  Top 0.254: IC7.2 55.88,33.02 46.99,41.91 46.99,71.76 45.72,73.03 R4.1
N$24
  Top 0.254: IC7.6 55.88,27.94 48.26,27.94 43.81,32.39 43.81,54.61 44.45,55.25 44.45,74.3 45.09,74.93 58.42,74.93 58.42,74.3 R5.1
N$25
  Top 0.254: IC7.10 62.23,29.21 60.96,29.21 60.96,36.83 67.31,43.18 67.31,69.22 71.12,73.03 R6.1
N$26
  Top 0.254: IC2.4 95.25,30.48 96.52,30.48 96.52,38.74 85.09,50.17 85.09,71.76 83.82,73.03 R7.1
N$27
  Top 0.254: IC2.8 100.33,26.67 98.42,26.67 98.42,71.12 96.52,73.03 R8.1
N$28
  Top 0.254: IC2.12 100.33,31.75 99.06,31.75 99.06,62.87 109.22,73.03 R9.1
N$29
  Top 0.254: IC8.4 133.35,30.48 134.62,30.48 134.62,34.93 133.35,36.2 123.83,36.2 123.83,71.12 121.92,73.03 R10.1
N$30
  Top 0.254: IC8.8 139.7,26.67 148.59,35.56 148.59,66.04 147.32,67.31 147.32,73.03 R11.1
N$31
  Top 0.254: R12.1 165.1,67.95 165.1,39.37 165.1,38.1 170.18,33.02 IC1.2
N$32
  Top 0.254: IC1.6 171.45,27.94 173.35,27.94 173.35,39.37 173.99,40.01 173.99,71.12 173.35,71.76 172.72,73.03 R13.1
N$33
  Top 0.254: IC1.10 176.53,29.21 174.62,29.21 174.62,38.1 175.9,38.1 175.9,73.66 184.78,73.66 R14.1 185.42,73.03
N$34
  Top 0.254: IC9.2 210.82,33.02 212.09,33.02 212.09,37.47 199.39,50.17 199.39,71.76 198.12,73.03 R15.1
N$35
  Top 0.254: 209.55,27.94 IC9.6 210.82,27.94 213.36,27.94 213.36,70.49 210.82,73.03 R16.1
N$36
  Top 0.254: R17.1 223.52,74.3 223.52,75.57 214.63,75.57 214.63,31.75 215.9,31.75 IC9.12
N$37
  Top 0.254: IC4.6 246.38,27.94 234.31,27.94 234.31,54.61 234.95,55.25 234.95,71.76 236.22,73.03 R18.1
N$38
  Top 0.254: R20.2 DTF.K
N$57
  Top 0.254: R21.2 DF.K
N$58
  Top 0.254: R22.2 W.K
N$59
  Top 0.254: R23.2 WC.K
N$60
  Top 0.254: R24.2 UTS.K
N$61
  Top 0.254: R25.2 BM.K
N$62
  Top 0.254: R26.2 RC.K
N$63
  Top 0.254: R27.2 D.K
N$64
  Top 0.254: R28.2 F.K
N$65
  Top 0.254: R29.2 CK.K
N$66
  Top 0.254: R30.2 IDLE.K
N$67
  Top 0.254: R31.2 MC0.K
N$68
  Top 0.254: R32.2 MC1.K
N$69
  Top 0.254: R33.2 MC2.K
N$70
  Top 0.254: R19.1 248.92,73.03 248.92,61.6 234.95,47.63 234.95,44.45 246.38,33.02 IC4.2
N$71
  Top 0.254: IC4.10 252.73,29.21 251.46,29.21 251.46,62.87 261.62,73.03 R20.1
N$72
  Top 0.254: IC10.6 297.18,27.94 285.75,39.37 285.75,71.76 287.02,73.03 R21.1
N$73
  Top 0.254: R23.1 302.26,63.5 302.26,29.21 303.53,29.21 IC10.10
N$74
  Top 0.254: IC10.2 297.18,33.02 296.55,33.66 296.55,53.34 298.45,55.25 298.45,71.76 299.72,73.03 R22.1
N$75
  Top 0.254: IC5.4 336.55,30.48 337.82,30.48 337.82,38.74 326.39,50.17 326.39,71.76 325.12,73.03 R24.1
N$76
  Top 0.254: R25.1 337.82,73.03 339.73,70.49 339.73,29.21 339.73,26.67 341.63,26.67 IC5.8
N$77
  Top 0.254: IC5.12 340.36,31.75 340.36,73.66 R26.1
N$78
  Top 0.254: IC11.4 374.65,30.48 375.92,30.48 375.92,38.74 364.49,50.17 364.49,71.76 363.22,73.03 R27.1
N$79
  Top 0.254: IC11.8 379.73,26.67 377.82,26.67 377.82,71.12 375.92,73.03 R28.1
N$80
  Top 0.254: IC11.12 381,31.75 386.71,37.47 386.71,54.61 387.35,55.25 387.35,71.76 388.62,73.03 R29.1
N$81
  Top 0.254: IC6.4 412.75,30.48 414.02,30.48 414.02,38.74 402.59,50.17 402.59,71.76 401.32,73.03 R30.1
N$82
  Top 0.254: IC6.8 417.83,26.67 415.93,26.67 415.93,36.83 416.56,37.47 416.56,62.23 415.93,62.87 415.93,71.76 414.02,73.03 R31.1
N$83
  Top 0.254: 417.19,64.14 416.56,63.5 | 417.19,64.14 R32.1 | IC6.10 417.83,29.21 416.56,29.21 416.56,36.2 417.19,36.83 417.19,64.14
N$84
  Top 0.254: R33.1 441.96,71.12 441.96,27.94 444.5,27.94 IC12.4
N$89
  Top 0.254: R34.1 DTB0.K
N$90
  Top 0.254: R35.1 DTB1.K
N$91
  Top 0.254: R36.1 DTB2.K
N$92
  Top 0.254: R37.1 DTB3.K
N$93
  Top 0.254: R38.1 DTB4.K
N$94
  Top 0.254: R39.1 DTB5.K
N$95
  Top 0.254: R40.1 DTB6.K
N$96
  Top 0.254: R41.1 DTB7.K
N$97
  Top 0.254: R42.1 DTB8.K
N$98
  Top 0.254: R43.1 DTB9.K
N$99
  Top 0.254: R44.1 DTB10.K
N$100
  Top 0.254: R45.1 DTB11.K
N$101
  Top 0.254: R46.1 WB0.K
N$102
  Top 0.254: R47.1 WB1.K
N$103
  Top 0.254: R48.1 WB2.K
N$104
  Top 0.254: LPB0.K R49.1
N$105
  Top 0.254: R50.1 LPB1.K
N$106
  Top 0.254: R51.1 LPB2.K
N$107
  Top 0.254: R52.1 LPB3.K
N$108
  Top 0.254: R53.1 LPB4.K
N$109
  Top 0.254: R54.1 LPB5.K
N$110
  Top 0.254: R55.1 C0.K
N$111
  Top 0.254: R56.1 C1.K
N$112
  Top 0.254: R57.1 MKT.K
N$113
  Top 0.254: R58.1 W0.K
N$114
  Top 0.254: R59.1 W1.K
N$115
  Top 0.254: R60.1 W2.K
N$116
  Top 0.254: R61.1 W3.K
N$117
  Top 0.254: R62.1 W4.K
N$118
  Top 0.254: R63.1 W5.K
N$119
  Top 0.254: R64.1 W6.K
N$120
  Top 0.254: R65.1 W7.K
N$121
  Top 0.254: R66.1 W8.K
N$122
  Top 0.254: WTM.K R67.1
N$123
  Top 0.254: R34.2 11.43,40.64 16.51,34.29 16.51,33.02 17.78,33.02 IC3.2
N$124
  Top 0.254: IC3.8 24.13,26.67 22.23,26.67 22.23,38.1 20.32,40.01 R35.2
N$125
  Top 0.254: R36.2 33.02,31.75 25.4,31.75 IC3.12
N$126
  Top 0.254: IC7.4 55.88,30.48 46.35,40.01 46.35,40.64 R37.2
N$127
  Top 0.254: R38.2 60.33,38.74 60.33,26.67 62.23,26.67 | 62.23,26.67 IC7.8 62.23,26.67
N$128
  Top 0.254: R39.2 71.12,31.75 63.5,31.75 IC7.12
N$129
  Top 0.254: R40.2 83.82,33.02 93.98,33.02 IC2.2
N$130
  Top 0.254: IC2.6 95.25,27.94 97.16,27.94 97.16,40.64 R41.2
N$131
  Top 0.254: IC2.10 101.6,29.21 109.22,36.83 109.22,40.01 R42.2
N$132
  Top 0.254: IC8.2 132.08,33.02 121.92,33.02 121.92,40.01 R43.2
N$133
  Top 0.254: R44.2 134.62,40.01 135.25,38.74 135.25,27.94 133.35,27.94 IC8.6
N$134
  Top 0.254: IC8.10 139.7,29.21 147.32,36.83 147.32,40.01 R45.2
N$135
  Top 0.254: IC8.12 139.7,31.75 146.05,38.1 146.05,74.3 146.69,74.93 156.21,74.93 156.21,45.09 160.02,41.28 R46.2
N$136
  Top 0.254: R47.2 172.72,30.48 171.45,30.48 IC1.4
N$137
  Top 0.254: IC1.8 177.8,26.67 185.42,34.29 185.42,40.01 R48.2
N$138
  Top 0.254: IC1.12 176.53,31.75 175.26,31.75 175.26,36.2 181.61,42.55 181.61,56.52 182.25,57.15 196.85,57.15 196.85,42.55 198.12,41.28 R49.2
N$139
  Top 0.254: IC9.4 210.82,30.48 212.72,30.48 212.72,38.1 210.82,40.01 R50.2
N$140
  Top 0.254: IC9.8 217.17,26.67 223.52,33.02 223.52,40.01 R51.2
N$141
  Top 0.254: R52.2 236.22,33.02 236.22,30.48 246.38,30.48 IC4.4
N$142
  Top 0.254: IC4.8 252.73,26.67 250.82,26.67 250.82,38.1 248.92,40.01 R53.2
N$143
  Top 0.254: R54.2 261.62,31.75 254,31.75 IC4.12
N$144
  Top 0.254: IC10.4 297.18,30.48 287.65,40.01 287.65,40.64 R55.2
N$145
  Top 0.254: IC10.8 303.53,26.67 301.62,26.67 301.62,38.1 299.72,40.01 R56.2
N$146
  Top 0.254: R57.2 312.42,31.75 304.8,31.75 IC10.12
N$147
  Top 0.254: R58.2 325.12,33.02 335.28,33.02 IC5.2
N$148
  Top 0.254: IC5.6 336.55,27.94 338.45,27.94 338.45,40.64 R59.2
N$149
  Top 0.254: IC5.10 342.9,29.21 350.52,36.83 350.52,40.01 R60.2
N$150
  Top 0.254: R61.2 363.22,33.02 373.38,33.02 IC11.2
N$151
  Top 0.254: IC11.6 374.65,27.94 376.56,27.94 376.56,40.64 R62.2
N$152
  Top 0.254: IC11.10 381,29.21 388.62,36.83 388.62,40.01 R63.2
N$153
  Top 0.254: R64.2 401.32,33.02 411.48,33.02 IC6.2
N$154
  Top 0.254: IC6.6 412.75,27.94 414.65,27.94 414.65,40.01 R65.2
N$155
  Top 0.254: R66.2 426.72,31.75 419.1,31.75 IC6.12
N$190
  Top 0.254: R67.2 450.85,41.91 450.85,57.15 448.31,57.15 443.23,52.07 443.23,30.48 444.5,30.48 IC12.2
PAR
  Top 0.254: IC9.1 209.55,34.29 190.5,34.29 187.96,34.29 187.96,33.02 169.54,14.61 168.28,14.61 168.12,14.45 100.33,14.45 100.33,9.53 99.06,8.26 SV1.5
SEL
  Top 0.254: 99.69,15.88 167,15.88 | 167,15.88 167.16,15.88 | IC1.11 177.8,30.48 184.15,36.83 184.15,41.28 184.78,41.91 186.69,41.91 186.69,34.29 168.28,15.88 167,15.88 | 97.79,15.88 97.79,12.7 97.79,9.53 96.52,8.26 SV1.7 | 97.79,15.88 99.69,15.88 | 97.79,15.88 99.69,15.88 | 97.79,15.88 99.69,15.88
ST_BLK_MK
  Top 0.254: IC5.9 342.9,27.94 343.54,27.31 343.54,26.04 342.26,24.77 316.87,24.77 316.87,19.69 306.07,19.69 306.07,9.53 304.8,8.26 SV2.19
ST_CK
  Top 0.254: IC11.13 379.73,33.02 378.46,33.02 378.46,65.41 387.99,74.93 390.52,74.93 390.52,23.5 381,14.61 378.46,14.61 316.23,14.61 316.23,9.53 314.96,8.26 SV2.11
ST_FINAL
  Top 0.254: SV2.13 312.42,8.26 313.69,9.53 313.69,15.88 378.46,15.88 381.63,17.15 381.63,27.31 381,27.94 IC11.9 379.73,27.94
ST_IDLE
  Top 0.254: IC6.3 411.48,31.75 392.43,13.34 318.77,13.34 318.77,9.53 317.5,8.26 SV2.9
ST_REV_CK
  Top 0.254: IC5.13 342.9,33.02 348.62,38.74 348.62,41.91 349.25,42.55 352.43,42.55 352.43,31.75 337.82,18.26 308.61,18.26 308.61,9.53 307.34,8.26 SV2.17
SWTM
  Top 0.254: 433.07,21.59 445.77,21.59 447.04,22.86 447.04,31.75 445.77,31.75 IC12.1 | 433.07,21.59 433.07,25.4 435.61,27.94 SWTM.2 | SV2.2 328.3,10.8 433.07,10.8 433.07,21.59
TIM
  Top 0.254: IC9.5 209.55,29.21 190.5,29.21 186.69,29.21 170.18,12.7 168.28,12.7 102.87,12.7 102.87,9.53 101.6,8.26 SV1.3
USR_00
  Top 0.254: SV1.35 38.1,7.62 37.47,7.62 20.32,24.77 20.32,29.21 19.05,29.21 | 19.05,29.21 IC3.5 19.05,29.21
USR_01
  Top 0.254: SV1.33 63.5,8.89 38.1,8.89 37.47,8.89 20.95,25.4 20.95,31.75 19.05,31.75 | 19.05,31.75 IC3.3 19.05,31.75
USR_02
  Top 0.254: IC3.11 25.4,30.48 26.67,30.48 43.81,13.34 64.77,13.34 64.77,9.53 66.04,8.26 SV1.31
UTS
  Top 0.254: IC5.3 335.28,31.75 315.6,31.75 315.6,20.96 303.53,20.96 303.53,9.53 302.26,8.26 SV2.21
VCC
  Top 0.254: W8.A 424.18,39.37 419.1,34.29 IC6.14 | W5.A 386.08,39.37 381,34.29 | 381,34.29 IC11.14 381,34.29 | 342.9,34.29 IC5.14 342.9,34.29 | MKT.A 309.88,39.37 304.8,34.29 IC10.14 | WTM.A 449.58,33.02 450.85,31.75 IC12.14 | DTB10.A 132.08,50.8 138.43,44.45 138.43,34.29 IC8.14 | LPB5.A 259.08,39.37 254,34.29 IC4.14 | WB2.A 182.88,39.37 177.8,34.29 IC1.14 | DTB5.A 68.58,39.37 63.5,34.29 IC7.14 | DTB2.A 30.48,39.37 25.4,34.29 IC3.14 | LPB2.A 220.98,38.1 217.17,34.29 IC9.14 | IC2.14 101.6,34.29 106.68,39.37 106.68,55.25 DTB8.A | 342.9,34.29 347.98,39.37 347.98,55.25 W2.A
  Bottom 0.254: USR0.A 6.35,90.17 16.51,90.17 | 16.51,90.17 USR1.A | 29.21,90.17 USR2.A | 29.21,90.17 16.51,90.17 | 41.91,90.17 MR0.A | 41.91,90.17 29.21,90.17 | 54.61,90.17 MR1.A | 54.61,90.17 41.91,90.17 | 67.31,90.17 FR0.A | 67.31,90.17 54.61,90.17 | 80.01,90.17 FR1.A | 80.01,90.17 67.31,90.17 | 92.71,90.17 FR2.A | 92.71,90.17 80.01,90.17 | 105.41,90.17 FR3.A | 105.41,90.17 92.71,90.17 | 118.11,90.17 ENI.A | 118.11,90.17 105.41,90.17 | 143.51,90.17 EF.A | 143.51,90.17 118.11,90.17 | 156.21,90.17 MK.A | 156.21,90.17 143.51,90.17 | 168.91,90.17 END.A | 168.91,90.17 156.21,90.17 | 181.61,90.17 SE.A | 181.61,90.17 168.91,90.17 | 194.31,90.17 PAR.A | 194.31,90.17 181.61,90.17 | 207.01,90.17 TIM.A | 207.01,90.17 194.31,90.17 | 219.71,90.17 MF0.A | 219.71,90.17 207.01,90.17 | 232.41,90.17 MF1.A | 232.41,90.17 219.71,90.17 | 245.11,90.17 MF2.A | 245.11,90.17 232.41,90.17 | 257.81,90.17 DTF.A | 257.81,90.17 245.11,90.17 | 283.21,90.17 DF.A | 283.21,90.17 257.81,90.17 | 295.91,90.17 W.A | 295.91,90.17 283.21,90.17 | 308.61,90.17 WC.A | 308.61,90.17 295.91,90.17 | 321.31,90.17 UTS.A | 321.31,90.17 308.61,90.17 | 334.01,90.17 BM.A | 334.01,90.17 321.31,90.17 | 346.71,90.17 RC.A | 346.71,90.17 334.01,90.17 | 359.41,90.17 D.A | 359.41,90.17 346.71,90.17 | 372.11,90.17 F.A | 372.11,90.17 359.41,90.17 | 384.81,90.17 CK.A | 384.81,90.17 372.11,90.17 | 397.51,90.17 IDLE.A | 397.51,90.17 384.81,90.17 | 410.21,90.17 MC0.A | 410.21,90.17 397.51,90.17 | 422.91,90.17 MC1.A | 422.91,90.17 410.21,90.17 | 422.91,90.17 435.61,90.17 MC2.A 436.88,57.15 | 295.91,57.15 285.75,57.15 C0.A 283.21,57.15 257.81,57.15 | 295.91,57.15 C1.A | 321.31,57.15 W0.A | 309.88,57.15 295.91,57.15 | 321.31,57.15 309.88,57.15 | 334.01,57.15 W1.A
  Bottom 0.254: 334.01,57.15 321.31,57.15 | 359.41,57.15 W3.A | 347.98,57.15 334.01,57.15 | 359.41,57.15 347.98,57.15 | 372.11,57.15 W4.A | 372.11,57.15 359.41,57.15 | 397.51,57.15 W6.A | 386.08,57.15 372.11,57.15 | 397.51,57.15 386.08,57.15 | 410.21,57.15 W7.A | 410.21,57.15 397.51,57.15 | WTM.A 448.31,57.15 436.88,57.15 | 424.18,57.15 410.21,57.15 | 436.88,57.15 424.18,57.15 | 309.88,57.15 MKT.A | 347.98,57.15 W2.A | 386.08,57.15 W5.A | 424.18,57.15 W8.A | DTB0.A 6.35,57.15 12.7,57.15 | 16.51,57.15 12.7,57.15 | 16.51,57.15 DTB1.A | 41.91,57.15 DTB3.A | 30.48,57.15 16.51,57.15 | 41.91,57.15 30.48,57.15 | 54.61,57.15 DTB4.A | 54.61,57.15 41.91,57.15 | 80.01,57.15 DTB6.A | 68.58,57.15 54.61,57.15 | 80.01,57.15 68.58,57.15 | 92.71,57.15 DTB7.A | 92.71,57.15 80.01,57.15 | 118.11,57.15 DTB9.A | 106.68,57.15 92.71,57.15 | 118.11,57.15 106.68,57.15 | 143.51,57.15 DTB11.A | 132.08,57.15 118.11,57.15 | 143.51,57.15 132.08,57.15 | 156.21,57.15 WB0.A | 156.21,57.15 143.51,57.15 | 168.91,57.15 WB1.A | 168.91,57.15 156.21,57.15 | 194.31,57.15 LPB0.A | 182.88,57.15 168.91,57.15 | 194.31,57.15 182.88,57.15 | 207.01,57.15 LPB1.A | 207.01,57.15 194.31,57.15 | 232.41,57.15 LPB3.A | 220.98,57.15 207.01,57.15 | 232.41,57.15 220.98,57.15 | 245.11,57.15 LPB4.A | 245.11,57.15 232.41,57.15 | 12.7,57.15 12.7,33.02 X4.1 | 8.89,20.32 X3.1 8.89,20.32 | X4.1 13.97,33.02 | 220.98,57.15 LPB2.A | 30.48,57.15 DTB2.A | 68.58,57.15 DTB5.A | 106.68,57.15 DTB8.A | 182.88,57.15 WB2.A | 257.81,57.15 LPB5.A | 257.81,57.15 245.11,57.15 | 132.08,57.15 DTB10.A | 8.89,20.32 16.51,27.94 16.51,33.02 13.97,33.02 | X4.1 13.97,33.02
W01
  Top 0.254: IC5.1 335.28,34.29 326.39,43.18 314.32,43.18 314.32,21.75 302.26,21.75 302.26,10.8 SV2.22
W02
  Top 0.254: IC5.5 335.28,29.21 316.23,29.21 316.23,20.32 304.8,20.32 304.8,10.8 SV2.20
W03
  Top 0.254: IC5.11 342.9,30.48 349.25,36.83 349.25,41.28 349.88,41.91 351.79,41.91 351.79,33.02 341.63,22.86 317.66,22.86 317.66,18.89 307.34,18.89 307.34,10.8 SV2.18
W04
  Top 0.254: IC11.1 373.38,34.29 364.49,43.18 353.06,43.18 353.06,31.12 338.45,17.78 309.88,17.78 SV2.16
W05
  Top 0.254: SV2.14 312.42,16.51 339.73,16.51 354.33,29.21 IC11.5
W06
  Top 0.254: IC11.11 381,30.48 387.35,36.83 387.35,41.28 387.99,41.91 389.89,41.91 389.89,24.13 381,15.24 377.19,15.24 314.96,15.24 314.96,10.8 SV2.12
W07
  Top 0.254: IC6.1 411.48,34.29 402.59,43.18 391.16,43.18 391.16,22.86 381,13.97 317.5,13.97 317.5,10.8 SV2.10
W08
  Top 0.254: IC6.5 411.48,29.21 410.21,29.21 393.06,12.7 320.04,12.7 320.04,10.8 SV2.8
W09
  Top 0.254: IC6.13 419.1,33.02 425.45,39.37 425.45,61.6 438.79,74.93 454.02,74.93 454.02,23.5 440.69,10.16 440.69,9.53 440.06,9.53 329.56,9.53 329.56,7.62 328.3,6.35 321.31,6.35 321.31,8.26 322.58,9.53 SV2.6
WB00
  Top 0.254: IC8.13 139.7,33.02 143.51,36.83 143.51,73.03 146.05,75.57 158.12,75.57 158.12,57.15 158.75,56.52 158.75,48.9 158.12,48.26 158.12,44.45 161.29,41.28 161.29,40.01 160.66,39.37 158.75,39.37 139.06,19.69 131.44,19.69 91.44,19.69 91.44,16.51 91.44,10.8 SV1.12
WB01
  Top 0.254: IC1.3 170.18,31.75 155.57,31.75 139.38,18.42 93.98,18.42 93.98,10.8 SV1.10
WB02
  Top 0.254: 176.53,27.94 IC1.9 176.53,27.94 | SV1.8 96.52,11.11 96.52,16.99 160.34,16.99 161.13,16.99 164.31,16.99 175.26,26.04 175.26,27.94 176.53,27.94
WC
  Top 0.254: SV2.23 298.45,8.89 298.45,22.86 307.34,22.86 307.34,30.48 304.8,30.48 IC10.11
WR_EN
  Top 0.254: SV2.25 295.91,8.89 295.91,24.13 300.99,24.13 300.99,34.29 298.45,34.29 IC10.1

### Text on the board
Document: USR | MR | FR | ENI | EF | MK | END | SE | PAR | TIM | MF | DTF | DF | W | UTS | STATE | WC | MC | 0 | 1 | 2 | 0 | 1 | 0 | 1 | 2 | 3 | 0 | 1 | 2 | BM | RC | D | F | CK | 0 | 1 | 2 | DTB | WB | LPB | C0 | C1 | MKT | WINDOW | WTM | 0 | 1 | 2 | 3 | 4 | 5 | 6 | 7 | 8 | 9 | 10 | 11 | 0 | 1 | 2 | 0 | 1 | 2 | 3 | 4 | 5 | 1 | 2 | 3 | 4 | 5 | 6 | 7 | 8 | 9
